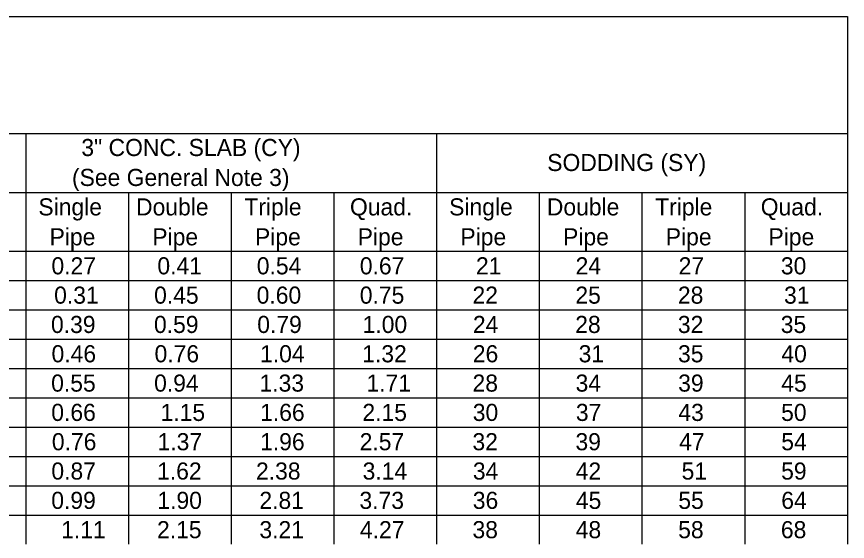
# Model space of a CAD drawing. Extents: x -1.3 to 14.6, y 0 to 8.4.
# Drawn here: x 10.062 to 13.46, y 6.282 to 8.43 of the extents above; entities that cross this region are included whole.
import ezdxf

# ---------------------------------------------------------------- set-up
doc = ezdxf.new("R2010")
doc.units = 0
doc.layers.add('Table', color=7, linetype='Continuous')

msp = doc.modelspace()

# ---------------------------------------------------------------- linework, layer by layer
at = {"layer": 'Table'}
msp.add_line((1.94, 8.43), (13.46, 8.43), dxfattribs=at)
for points in [[(13.46, 8.43), (13.46, 7.83), (13.46, 7.47), (13.46, 7.35), (13.46, 7.23), (13.46, 7.11), (13.46, 6.99), (13.46, 6.87), (13.46, 6.75), (13.46, 6.63), (13.46, 6.51), (13.46, 6.39), (13.46, 6.27)], [(13.46, 7.95), (11.78, 7.95), (10.1, 7.95), (8.42, 7.95), (8.06, 7.95), (6.38, 7.95), (6.02, 7.95), (5.66, 7.95), (5.42, 7.95), (4.94, 7.95), (4.52, 7.95), (4.04, 7.95), (3.62, 7.95), (3.2, 7.95), (2.9, 7.95), (2.6, 7.95), (2.3, 7.95), (1.94, 7.95)], [(10.1, 7.95), (10.1, 7.71), (10.1, 7.47), (10.1, 7.35), (10.1, 7.23), (10.1, 7.11), (10.1, 6.99), (10.1, 6.87), (10.1, 6.75), (10.1, 6.63), (10.1, 6.51), (10.1, 6.39), (10.1, 6.27)], [(11.78, 7.95), (11.78, 7.71), (11.78, 7.47), (11.78, 7.35), (11.78, 7.23), (11.78, 7.11), (11.78, 6.99), (11.78, 6.87), (11.78, 6.75), (11.78, 6.63), (11.78, 6.51), (11.78, 6.39), (11.78, 6.27)], [(8.42, 7.71), (8.84, 7.71), (9.26, 7.71), (9.68, 7.71), (10.1, 7.71), (10.52, 7.71), (10.94, 7.71), (11.36, 7.71), (11.78, 7.71), (12.2, 7.71), (12.62, 7.71), (13.04, 7.71), (13.46, 7.71)], [(10.52, 7.71), (10.52, 7.47), (10.52, 7.35), (10.52, 7.23), (10.52, 7.11), (10.52, 6.99), (10.52, 6.87), (10.52, 6.75), (10.52, 6.63), (10.52, 6.51), (10.52, 6.39), (10.52, 6.27)], [(10.94, 7.71), (10.94, 7.47), (10.94, 7.35), (10.94, 7.23), (10.94, 7.11), (10.94, 6.99), (10.94, 6.87), (10.94, 6.75), (10.94, 6.63), (10.94, 6.51), (10.94, 6.39), (10.94, 6.27)], [(11.36, 7.71), (11.36, 7.47), (11.36, 7.35), (11.36, 7.23), (11.36, 7.11), (11.36, 6.99), (11.36, 6.87), (11.36, 6.75), (11.36, 6.63), (11.36, 6.51), (11.36, 6.39), (11.36, 6.27)], [(12.2, 7.71), (12.2, 7.47), (12.2, 7.35), (12.2, 7.23), (12.2, 7.11), (12.2, 6.99), (12.2, 6.87), (12.2, 6.75), (12.2, 6.63), (12.2, 6.51), (12.2, 6.39), (12.2, 6.27)], [(12.62, 7.71), (12.62, 7.47), (12.62, 7.35), (12.62, 7.23), (12.62, 7.11), (12.62, 6.99), (12.62, 6.87), (12.62, 6.75), (12.62, 6.63), (12.62, 6.51), (12.62, 6.39), (12.62, 6.27)], [(13.04, 7.71), (13.04, 7.47), (13.04, 7.35), (13.04, 7.23), (13.04, 7.11), (13.04, 6.99), (13.04, 6.87), (13.04, 6.75), (13.04, 6.63), (13.04, 6.51), (13.04, 6.39), (13.04, 6.27)], [(4.04, 7.47), (4.52, 7.47), (4.94, 7.47), (5.42, 7.47), (5.66, 7.47), (6.02, 7.47), (6.38, 7.47), (6.8, 7.47), (7.22, 7.47), (7.64, 7.47), (8.06, 7.47), (8.42, 7.47), (8.84, 7.47), (9.26, 7.47), (9.68, 7.47), (10.1, 7.47), (10.52, 7.47), (10.94, 7.47), (11.36, 7.47), (11.78, 7.47), (12.2, 7.47), (12.62, 7.47), (13.04, 7.47), (13.46, 7.47)], [(4.04, 7.35), (4.52, 7.35), (4.94, 7.35), (5.42, 7.35), (5.66, 7.35), (6.02, 7.35), (6.38, 7.35), (6.8, 7.35), (7.22, 7.35), (7.64, 7.35), (8.06, 7.35), (8.42, 7.35), (8.84, 7.35), (9.26, 7.35), (9.68, 7.35), (10.1, 7.35), (10.52, 7.35), (10.94, 7.35), (11.36, 7.35), (11.78, 7.35), (12.2, 7.35), (12.62, 7.35), (13.04, 7.35), (13.46, 7.35)], [(4.04, 7.23), (4.52, 7.23), (4.94, 7.23), (5.42, 7.23), (5.66, 7.23), (6.02, 7.23), (6.38, 7.23), (6.8, 7.23), (7.22, 7.23), (7.64, 7.23), (8.06, 7.23), (8.42, 7.23), (8.84, 7.23), (9.26, 7.23), (9.68, 7.23), (10.1, 7.23), (10.52, 7.23), (10.94, 7.23), (11.36, 7.23), (11.78, 7.23), (12.2, 7.23), (12.62, 7.23), (13.04, 7.23), (13.46, 7.23)], [(4.04, 7.11), (4.52, 7.11), (4.94, 7.11), (5.42, 7.11), (5.66, 7.11), (6.02, 7.11), (6.38, 7.11), (6.8, 7.11), (7.22, 7.11), (7.64, 7.11), (8.06, 7.11), (8.42, 7.11), (8.84, 7.11), (9.26, 7.11), (9.68, 7.11), (10.1, 7.11), (10.52, 7.11), (10.94, 7.11), (11.36, 7.11), (11.78, 7.11), (12.2, 7.11), (12.62, 7.11), (13.04, 7.11), (13.46, 7.11)], [(4.04, 6.99), (4.52, 6.99), (4.94, 6.99), (5.42, 6.99), (5.66, 6.99), (6.02, 6.99), (6.38, 6.99), (6.8, 6.99), (7.22, 6.99), (7.64, 6.99), (8.06, 6.99), (8.42, 6.99), (8.84, 6.99), (9.26, 6.99), (9.68, 6.99), (10.1, 6.99), (10.52, 6.99), (10.94, 6.99), (11.36, 6.99), (11.78, 6.99), (12.2, 6.99), (12.62, 6.99), (13.04, 6.99), (13.46, 6.99)], [(4.04, 6.87), (4.52, 6.87), (4.94, 6.87), (5.42, 6.87), (5.66, 6.87), (6.02, 6.87), (6.38, 6.87), (6.8, 6.87), (7.22, 6.87), (7.64, 6.87), (8.06, 6.87), (8.42, 6.87), (8.84, 6.87), (9.26, 6.87), (9.68, 6.87), (10.1, 6.87), (10.52, 6.87), (10.94, 6.87), (11.36, 6.87), (11.78, 6.87), (12.2, 6.87), (12.62, 6.87), (13.04, 6.87), (13.46, 6.87)], [(4.04, 6.75), (4.52, 6.75), (4.94, 6.75), (5.42, 6.75), (5.66, 6.75), (6.02, 6.75), (6.38, 6.75), (6.8, 6.75), (7.22, 6.75), (7.64, 6.75), (8.06, 6.75), (8.42, 6.75), (8.84, 6.75), (9.26, 6.75), (9.68, 6.75), (10.1, 6.75), (10.52, 6.75), (10.94, 6.75), (11.36, 6.75), (11.78, 6.75), (12.2, 6.75), (12.62, 6.75), (13.04, 6.75), (13.46, 6.75)], [(4.04, 6.63), (4.52, 6.63), (4.94, 6.63), (5.42, 6.63), (5.66, 6.63), (6.02, 6.63), (6.38, 6.63), (6.8, 6.63), (7.22, 6.63), (7.64, 6.63), (8.06, 6.63), (8.42, 6.63), (8.84, 6.63), (9.26, 6.63), (9.68, 6.63), (10.1, 6.63), (10.52, 6.63), (10.94, 6.63), (11.36, 6.63), (11.78, 6.63), (12.2, 6.63), (12.62, 6.63), (13.04, 6.63), (13.46, 6.63)], [(4.04, 6.51), (4.52, 6.51), (4.94, 6.51), (5.42, 6.51), (5.66, 6.51), (6.02, 6.51), (6.38, 6.51), (6.8, 6.51), (7.22, 6.51), (7.64, 6.51), (8.06, 6.51), (8.42, 6.51), (8.84, 6.51), (9.26, 6.51), (9.68, 6.51), (10.1, 6.51), (10.52, 6.51), (10.94, 6.51), (11.36, 6.51), (11.78, 6.51), (12.2, 6.51), (12.62, 6.51), (13.04, 6.51), (13.46, 6.51)], [(4.04, 6.39), (4.52, 6.39), (4.94, 6.39), (5.42, 6.39), (5.66, 6.39), (6.02, 6.39), (6.38, 6.39), (6.8, 6.39), (7.22, 6.39), (7.64, 6.39), (8.06, 6.39), (8.42, 6.39), (8.84, 6.39), (9.26, 6.39), (9.68, 6.39), (10.1, 6.39), (10.52, 6.39), (10.94, 6.39), (11.36, 6.39), (11.78, 6.39), (12.2, 6.39), (12.62, 6.39), (13.04, 6.39), (13.46, 6.39)]]:
    msp.add_lwpolyline(points, dxfattribs=at)

# ---------------------------------------------------------------- texts
for s, p in [('3" CONC. SLAB (CY)', (10.3271, 7.8592)), ('SODDING (SY)', (12.2325, 7.7979)), ('(See General Note 3)', (10.2888, 7.7367)), ('Single', (10.1514, 7.6162)), ('Double', (10.5509, 7.6162)), ('Triple', (10.9937, 7.6162)), ('Quad.', (11.4257, 7.6162)), ('Single', (11.8314, 7.6162)), ('Double', (12.2309, 7.6162)), ('Triple', (12.6737, 7.6162)), ('Quad.', (13.1057, 7.6162)), ('Pipe', (10.1973, 7.4937)), ('Pipe', (10.6173, 7.4937)), ('Pipe', (11.0373, 7.4937)), ('Pipe', (11.4573, 7.4937)), ('Pipe', (11.8773, 7.4937)), ('Pipe', (12.2973, 7.4937)), ('Pipe', (12.7173, 7.4937)), ('Pipe', (13.1373, 7.4937)), ('0.27', (10.2049, 7.375)), ('0.41', (10.6381, 7.375)), ('0.54', (11.0446, 7.375)), ('0.67', (11.466, 7.375)), ('0.31', (10.2159, 7.255)), ('0.45', (10.6247, 7.255)), ('0.60', (11.0441, 7.255)), ('0.75', (11.4659, 7.255)), ('0.39', (10.203, 7.135)), ('0.59', (10.6242, 7.135)), ('0.79', (11.0465, 7.135)), ('1.00', (11.4775, 7.135)), ('0.46', (10.2052, 7.015)), ('0.76', (10.6265, 7.015)), ('1.04', (11.0581, 7.015)), ('1.32', (11.4758, 7.015)), ('0.55', (10.2037, 6.895)), ('0.94', (10.6247, 6.895)), ('1.33', (11.0557, 6.895)), ('1.71', (11.4933, 6.895)), ('0.66', (10.2042, 6.775)), ('1.15', (10.6511, 6.775)), ('1.66', (11.0582, 6.775)), ('2.15', (11.4766, 6.775)), ('0.76', (10.2065, 6.655)), ('1.37', (10.6388, 6.655)), ('1.96', (11.0582, 6.655)), ('2.57', (11.4654, 6.655)), ('0.87', (10.2046, 6.535)), ('1.62', (10.6369, 6.535)), ('2.38', (11.0414, 6.535)), ('3.14', (11.4775, 6.535)), ('0.99', (10.2042, 6.415)), ('1.90', (10.6381, 6.415)), ('2.81', (11.0553, 6.415)), ('3.73', (11.4645, 6.415)), ('1.11', (10.2445, 6.295)), ('2.15', (10.6366, 6.295)), ('3.21', (11.0554, 6.295)), ('4.27', (11.4664, 6.295))]:
    msp.add_text(s, height=0.07, dxfattribs=at).set_placement(p)
for s, p in [('21', (11.941, 7.375)), ('24', (12.3485, 7.375)), ('27', (12.7698, 7.375)), ('30', (13.1879, 7.375)), ('22', (11.9268, 7.255)), ('25', (12.3475, 7.255)), ('28', (12.7669, 7.255)), ('31', (13.2009, 7.255)), ('24', (11.9285, 7.135)), ('28', (12.3469, 7.135)), ('32', (12.7667, 7.135)), ('35', (13.1874, 7.135)), ('26', (11.9281, 7.015)), ('31', (12.3609, 7.015)), ('35', (12.7674, 7.015)), ('40', (13.19, 7.015)), ('28', (11.9269, 6.895)), ('34', (12.3484, 6.895)), ('39', (12.768, 6.895)), ('45', (13.1896, 6.895)), ('30', (11.9279, 6.775)), ('37', (12.3497, 6.775)), ('43', (12.7688, 6.775)), ('50', (13.189, 6.775)), ('32', (11.9267, 6.655)), ('39', (12.348, 6.655)), ('47', (12.7719, 6.655)), ('54', (13.1896, 6.655)), ('34', (11.9284, 6.535)), ('42', (12.3489, 6.535)), ('51', (12.782, 6.535)), ('59', (13.1891, 6.535)), ('36', (11.928, 6.415)), ('45', (12.3496, 6.415)), ('55', (12.7686, 6.415)), ('64', (13.1896, 6.415)), ('38', (11.9268, 6.295)), ('48', (12.349, 6.295)), ('58', (12.768, 6.295)), ('68', (13.188, 6.295))]:
    msp.add_text(s, height=0.07, rotation=0, dxfattribs=at).set_placement(p)

doc.saveas('drawing.dxf')
